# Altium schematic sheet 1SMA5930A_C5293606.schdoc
size 127 x 101 mm
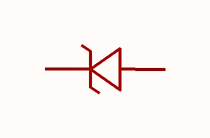
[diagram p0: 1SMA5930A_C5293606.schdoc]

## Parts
D?  1sma5930a_c5293606  [SMAG_L4.3-W2.6-LS5.3-RD]  (value not drawn)

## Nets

Not connected (* = marked no-connect by the designer): D? 1(K) 2(A)

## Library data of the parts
D? = 1sma5930a_c5293606: 二极管配置:1个独立式;稳压值(标称值):16V;稳压值(范围值):15.2V~16.8V;耗散功率(Pd):1.5W;; Manufacturer: CJ(江苏长电/长晶); AddInBom: yes; ModelId: 3cd8680d946b497db8ea5837610a9736; ModelTransform: 208.661,102.362,0,0,0,0,0,0,0; Diode Configuration: 1个独立式; Zener Voltage(Nom): 16V; Reverse Leakage Current (Ir): 500nA@12.2V; Pd - Power Dissipation: 1.5W; Impedance(Zzt): 10Ω; Impedance(Zzk): 600Ω; Operating Junction Temperature Range: -55℃~+150℃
